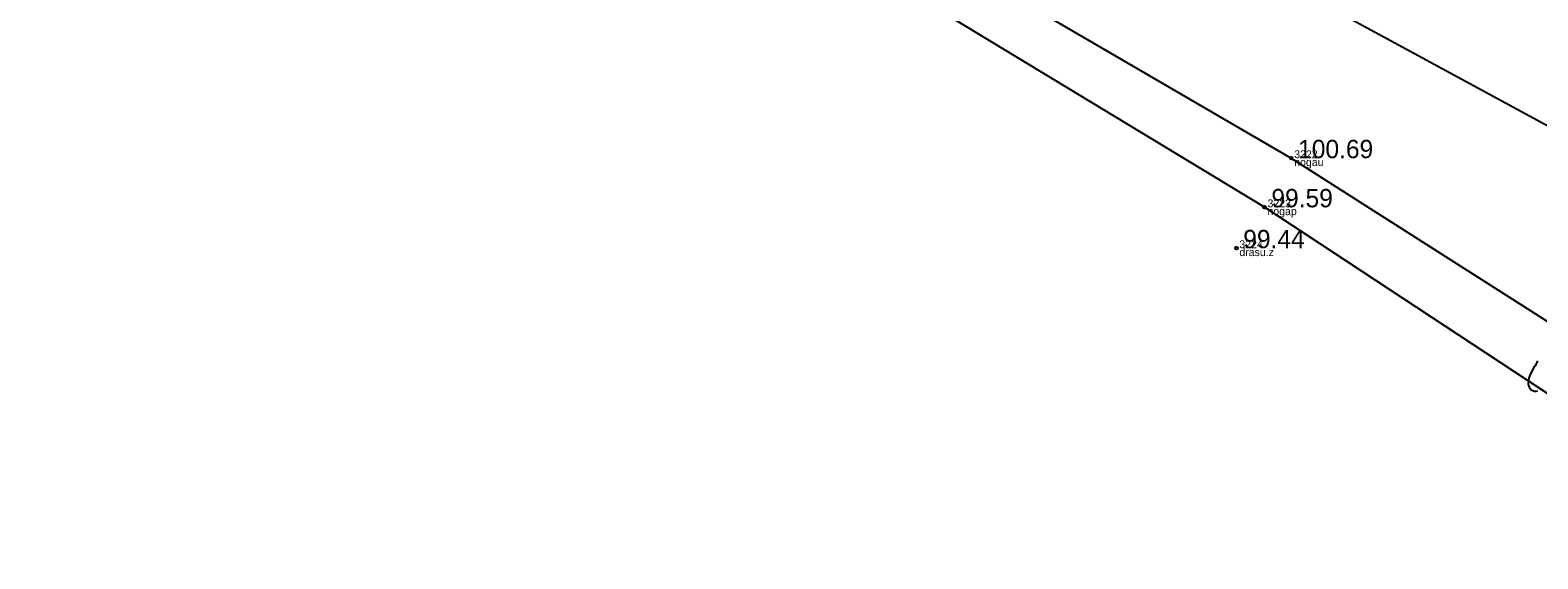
# Model space of a CAD drawing. Extents: x 614911 to 615803, y 262110 to 264311.
# Drawn here: x 615533.1 to 615590.6, y 263920.9 to 263941.1 of the extents above; entities that cross this region are included whole.
import ezdxf

# ---------------------------------------------------------------- set-up
doc = ezdxf.new("R2010")
doc.units = 0
for name, color, linetype in [('Level 1', 7, 'Continuous'), ('Level 31', 7, 'Continuous'), ('Level 37', 7, 'Continuous'), ('Level 53', 7, 'Continuous'), ('Level 54', 7, 'Continuous'), ('Level 57', 7, 'Continuous'), ('Level 58', 7, 'Continuous')]:
    doc.layers.add(name, color=color, linetype=linetype)

msp = doc.modelspace()

# ---------------------------------------------------------------- linework, layer by layer
at = {"layer": 'Level 1'}
for centre, radius, start, end in [((615591.141, 263927.624), 0.89, 151.75703, 179.91384), ((615603.242, 263920.603), 14.88, 148.48442, 149.99014), ((615590.2, 263928.637), 0.439, 324.38368, 341.71196), ((615590.541, 263927.63), 0.29, 181.07816, 285.2823)]:
    msp.add_arc(centre, radius, start, end, dxfattribs=at)
at = {"layer": 'Level 31'}
for points in [[(615596.006, 263921.78), (615592.365, 263926.331), (615580.198, 263934.354), (615551.302, 263951.868)], [(615566.06, 263945.065), (615581.217, 263936.227), (615592.943, 263928.756), (615595.838, 263926.84), (615596.434, 263923.358)]]:
    msp.add_lwpolyline(points, dxfattribs=at)
at = {"layer": 'Level 37'}
msp.add_lwpolyline([(615533.131, 263961.764), (615535.802, 263964.254), (615538.177, 263964.684), (615539.79, 263964.811), (615542.067, 263963.909), (615553.832, 263957.485), (615568.498, 263949.546), (615571.918, 263947.737), (615583.355, 263941.61), (615598.717, 263933.282), (615602.689, 263931.223), (615603.343, 263930.446), (615603.485, 263929.603), (615597.586, 263920.945)], dxfattribs=at)
at = {"layer": 'Level 57'}
for centre in [(615581.217, 263936.227), (615580.198, 263934.354), (615579.125, 263932.793)]:
    msp.add_circle(centre, 0.05, dxfattribs=at)
at = {"layer": 'Level 58'}
for centre in [(615581.217, 263936.227), (615580.198, 263934.354), (615579.125, 263932.793)]:
    msp.add_circle(centre, 0.05, dxfattribs=at)

# ---------------------------------------------------------------- texts
at = {"layer": 'Level 53'}
for s, p in [(' nogau', (615581.217, 263935.927)), (' nogap', (615580.198, 263934.054)), (' drasu.z', (615579.125, 263932.493))]:
    msp.add_text(s, height=0.3, dxfattribs=at).set_placement(p)
at = {"layer": 'Level 54'}
for s, p in [(' 3222', (615581.217, 263936.227)), (' 3223', (615580.198, 263934.354)), (' 3224', (615579.125, 263932.793))]:
    msp.add_text(s, height=0.3, dxfattribs=at).set_placement(p)
at = {"layer": 'Level 58'}
for s, p in [(' 100.69', (615581.217, 263936.227)), (' 99.59', (615580.198, 263934.354)), (' 99.44', (615579.125, 263932.793))]:
    msp.add_text(s, height=0.7, dxfattribs=at).set_placement(p)

doc.saveas('drawing.dxf')
